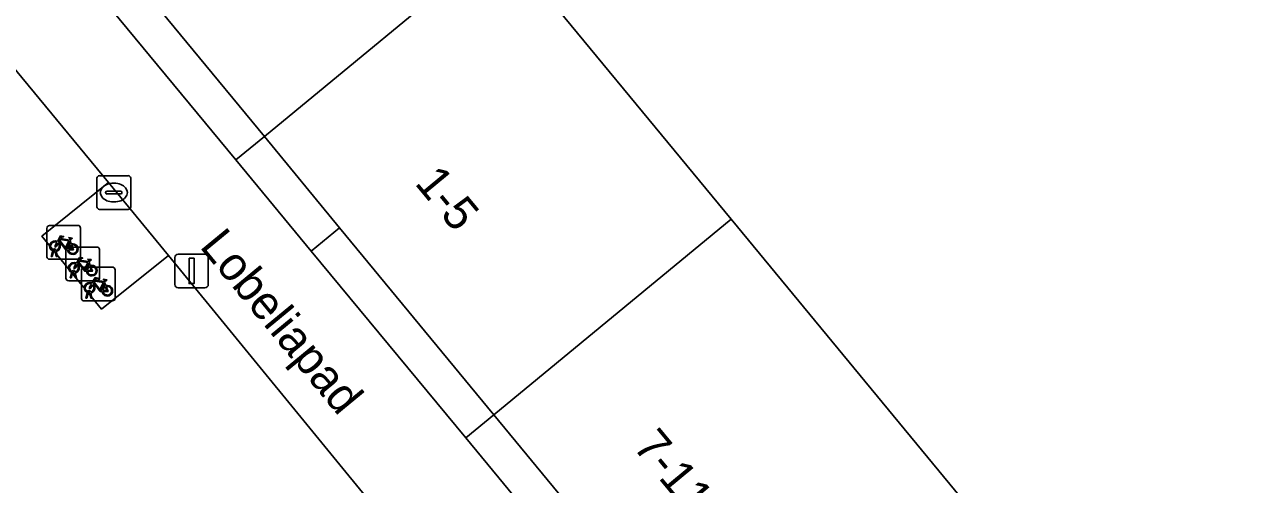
# Model space of a CAD drawing. Extents: x 162344 to 162869, y 381217 to 381818.
# Drawn here: x 162459.05 to 162495.73, y 381719.32 to 381732.95 of the extents above; entities that cross this region are included whole.
import ezdxf

# ---------------------------------------------------------------- set-up
doc = ezdxf.new("R2010")
doc.units = 0
for name, color, linetype in [('IMGEO_Fietsenrek', 7, 'Continuous'), ('IMGEO_Groenvoorziening', 7, 'Continuous'), ('IMGEO_Kolk', 7, 'Continuous'), ('IMGEO_Lichtmast', 7, 'Continuous'), ('IMGEO_Openbare_ruimte_label', 7, 'Continuous'), ('IMGEO_Pand', 7, 'Continuous'), ('IMGEO_Pand_nummerreeks', 7, 'Continuous'), ('IMGEO_Voetpad_open', 7, 'Continuous')]:
    doc.layers.add(name, color=color, linetype=linetype)

msp = doc.modelspace()

# ---------------------------------------------------------------- linework, layer by layer
at = {"layer": 'IMGEO_Fietsenrek'}
for p, q in [((162459.708, 381726.069), (162459.708, 381726.91)), ((162459.708, 381726.91), (162459.708, 381726.069)), ((162459.783, 381726.994), (162460.624, 381726.994)), ((162460.624, 381726.994), (162459.783, 381726.994)), ((162460.708, 381726.919), (162460.708, 381726.078)), ((162460.708, 381726.078), (162460.708, 381726.919)), ((162460.346, 381726.355), (162461.187, 381726.355)), ((162461.187, 381726.355), (162460.346, 381726.355)), ((162460.395, 381726.543), (162460.431, 381726.448)), ((162461.271, 381726.28), (162461.271, 381725.439)), ((162461.271, 381725.439), (162461.271, 381726.28)), ((162460.633, 381725.994), (162459.792, 381725.994)), ((162459.792, 381725.994), (162460.633, 381725.994)), ((162459.835, 381726.078), (162459.874, 381726.238)), ((162459.869, 381726.078), (162459.835, 381726.078)), ((162459.904, 381726.226), (162459.869, 381726.078)), ((162459.946, 381726.25), (162459.945, 381726.254)), ((162459.987, 381726.078), (162459.953, 381726.22)), ((162459.977, 381726.261), (162459.978, 381726.254)), ((162459.985, 381726.224), (162460.02, 381726.078)), ((162460.02, 381726.078), (162459.987, 381726.078)), ((162460.271, 381725.43), (162460.271, 381726.271)), ((162460.271, 381726.271), (162460.271, 381725.43)), ((162460.398, 381725.439), (162460.437, 381725.599)), ((162460.467, 381725.587), (162460.432, 381725.439)), ((162460.509, 381725.611), (162460.508, 381725.615)), ((162460.55, 381725.439), (162460.516, 381725.581)), ((162460.54, 381725.622), (162460.541, 381725.615)), ((162460.548, 381725.585), (162460.583, 381725.439)), ((162460.733, 381724.834), (162460.733, 381725.675)), ((162460.733, 381725.675), (162460.733, 381724.834)), ((162460.808, 381725.759), (162461.649, 381725.759)), ((162461.649, 381725.759), (162460.808, 381725.759)), ((162460.958, 381725.904), (162460.994, 381725.809)), ((162461.733, 381725.684), (162461.733, 381724.843)), ((162461.733, 381724.843), (162461.733, 381725.684)), ((162461.196, 381725.355), (162460.355, 381725.355)), ((162460.355, 381725.355), (162461.196, 381725.355)), ((162460.432, 381725.439), (162460.398, 381725.439)), ((162460.583, 381725.439), (162460.55, 381725.439)), ((162461.42, 381725.308), (162461.456, 381725.213)), ((162460.86, 381724.843), (162460.899, 381725.003)), ((162460.894, 381724.843), (162460.86, 381724.843)), ((162460.929, 381724.991), (162460.894, 381724.843)), ((162460.971, 381725.015), (162460.97, 381725.019)), ((162461.012, 381724.843), (162460.978, 381724.985)), ((162461.002, 381725.026), (162461.003, 381725.019)), ((162461.01, 381724.989), (162461.045, 381724.843)), ((162461.045, 381724.843), (162461.012, 381724.843)), ((162461.658, 381724.759), (162460.817, 381724.759)), ((162460.817, 381724.759), (162461.658, 381724.759))]:
    msp.add_line(p, q, dxfattribs=at)
for points in [[(162460.021, 381726.52), (162460.116, 381726.684), (162460.202, 381726.67), (162460.204, 381726.661), (162460.148, 381726.65), (162460.121, 381726.605), (162460.377, 381726.564)], [(162460.042, 381726.468), (162459.99, 381726.378), (162459.95, 381726.353), (162459.951, 381726.4), (162460.006, 381726.494)], [(162460.317, 381726.276), (162460.267, 381726.276), (162460.076, 381726.527), (162460.057, 381726.495)], [(162460.364, 381726.539), (162460.107, 381726.58), (162460.09, 381726.551), (162460.257, 381726.331), (162460.364, 381726.539)], [(162460.412, 381726.441), (162460.382, 381726.518), (162460.273, 381726.3), (162460.316, 381726.3)], [(162460.346, 381726.3), (162460.466, 381726.299), (162460.422, 381726.413)], [(162460.442, 381726.42), (162460.497, 381726.275), (162460.347, 381726.275)], [(162460.377, 381726.564), (162460.402, 381726.613), (162460.396, 381726.617), (162460.373, 381726.621), (162460.361, 381726.628), (162460.36, 381726.631), (162460.362, 381726.636), (162460.457, 381726.621), (162460.459, 381726.611), (162460.449, 381726.598), (162460.437, 381726.592), (162460.423, 381726.598), (162460.395, 381726.543)], [(162460.584, 381725.881), (162460.679, 381726.045), (162460.765, 381726.031), (162460.767, 381726.022), (162460.711, 381726.011), (162460.684, 381725.966), (162460.94, 381725.925)], [(162460.927, 381725.9), (162460.67, 381725.941), (162460.653, 381725.912), (162460.82, 381725.692), (162460.927, 381725.9)], [(162460.94, 381725.925), (162460.965, 381725.974), (162460.959, 381725.978), (162460.936, 381725.982), (162460.924, 381725.989), (162460.923, 381725.992), (162460.925, 381725.997), (162461.02, 381725.982), (162461.022, 381725.972), (162461.012, 381725.959), (162461, 381725.953), (162460.986, 381725.959), (162460.958, 381725.904)], [(162460.605, 381725.829), (162460.553, 381725.739), (162460.513, 381725.714), (162460.514, 381725.761), (162460.569, 381725.855)], [(162460.88, 381725.637), (162460.83, 381725.637), (162460.639, 381725.888), (162460.62, 381725.856)], [(162460.975, 381725.802), (162460.945, 381725.879), (162460.836, 381725.661), (162460.879, 381725.661)], [(162460.909, 381725.661), (162461.029, 381725.66), (162460.985, 381725.774)], [(162461.005, 381725.781), (162461.06, 381725.636), (162460.91, 381725.636)], [(162461.067, 381725.233), (162461.015, 381725.143), (162460.975, 381725.118), (162460.976, 381725.165), (162461.031, 381725.259)], [(162461.046, 381725.285), (162461.141, 381725.449), (162461.227, 381725.435), (162461.229, 381725.426), (162461.173, 381725.415), (162461.146, 381725.37), (162461.402, 381725.329)], [(162461.342, 381725.041), (162461.292, 381725.041), (162461.101, 381725.292), (162461.082, 381725.26)], [(162461.389, 381725.304), (162461.132, 381725.345), (162461.115, 381725.316), (162461.282, 381725.096), (162461.389, 381725.304)], [(162461.437, 381725.206), (162461.407, 381725.283), (162461.298, 381725.065), (162461.341, 381725.065)], [(162461.371, 381725.065), (162461.491, 381725.064), (162461.447, 381725.178)], [(162461.467, 381725.185), (162461.522, 381725.04), (162461.372, 381725.04)], [(162461.402, 381725.329), (162461.427, 381725.378), (162461.421, 381725.382), (162461.398, 381725.386), (162461.386, 381725.393), (162461.385, 381725.396), (162461.387, 381725.401), (162461.482, 381725.386), (162461.484, 381725.376), (162461.474, 381725.363), (162461.462, 381725.357), (162461.448, 381725.363), (162461.42, 381725.308)]]:
    msp.add_lwpolyline(points, dxfattribs=at)
for centre, radius, start, end in [((162459.786, 381726.916), 0.0779, 92.4484, 184.2845), ((162459.786, 381726.916), 0.0779, 92.4484, 184.2845), ((162460.63, 381726.916), 0.0779, 2.4484, 94.2845), ((162460.63, 381726.916), 0.0779, 2.4484, 94.2845), ((162459.948, 381726.379), 0.159, 62.6766, 242.1369), ((162459.948, 381726.379), 0.129, 63.3192, 238.903), ((162459.928, 381726.25), 0.0499, 12.8025, 158.6934), ((162459.948, 381726.379), 0.129, 283.6043, 43.4302), ((162459.948, 381726.379), 0.159, 283.5766, 46.6042), ((162460.349, 381726.277), 0.0779, 92.4484, 184.2845), ((162460.349, 381726.277), 0.0779, 92.4484, 184.2845), ((162460.475, 381726.295), 0.159, 113.3408, 178.3217), ((162460.475, 381726.295), 0.159, 187.0065, 105.7708), ((162460.475, 381726.295), 0.129, 113.923, 177.9556), ((162460.475, 381726.295), 0.129, 188.6715, 104.5883), ((162461.193, 381726.277), 0.0779, 2.4484, 94.2845), ((162461.193, 381726.277), 0.0779, 2.4484, 94.2845), ((162459.786, 381726.072), 0.0779, 182.4484, 274.2845), ((162459.786, 381726.072), 0.0779, 182.4484, 274.2845), ((162459.948, 381726.379), 0.159, 253.9967, 271.7867), ((162459.928, 381726.25), 0.0174, 12.8025, 163.4502), ((162459.948, 381726.379), 0.129, 253.415, 269.0204), ((162460.63, 381726.072), 0.0779, 272.4484, 4.2845), ((162460.63, 381726.072), 0.0779, 272.4484, 4.2845), ((162460.511, 381725.74), 0.159, 62.6766, 242.1369), ((162460.511, 381725.74), 0.129, 63.3192, 238.903), ((162460.491, 381725.611), 0.0499, 12.8025, 158.6934), ((162460.511, 381725.74), 0.159, 253.9967, 271.7867), ((162460.491, 381725.611), 0.0174, 12.8025, 163.4502), ((162460.511, 381725.74), 0.129, 253.415, 269.0204), ((162460.511, 381725.74), 0.129, 283.6043, 43.4302), ((162460.511, 381725.74), 0.159, 283.5766, 46.6042), ((162460.811, 381725.681), 0.0779, 92.4484, 184.2845), ((162460.811, 381725.681), 0.0779, 92.4484, 184.2845), ((162461.038, 381725.656), 0.159, 113.3408, 178.3217), ((162461.038, 381725.656), 0.159, 187.0065, 105.7708), ((162461.038, 381725.656), 0.129, 113.923, 177.9556), ((162461.038, 381725.656), 0.129, 188.6715, 104.5883), ((162461.655, 381725.681), 0.0779, 2.4484, 94.2845), ((162461.655, 381725.681), 0.0779, 2.4484, 94.2845), ((162460.349, 381725.433), 0.0779, 182.4484, 274.2845), ((162460.349, 381725.433), 0.0779, 182.4484, 274.2845), ((162460.973, 381725.144), 0.159, 62.6766, 242.1369), ((162460.973, 381725.144), 0.129, 63.3192, 238.903), ((162460.973, 381725.144), 0.129, 283.6043, 43.4302), ((162460.973, 381725.144), 0.159, 283.5766, 46.6042), ((162461.193, 381725.433), 0.0779, 272.4484, 4.2845), ((162461.193, 381725.433), 0.0779, 272.4484, 4.2845), ((162461.5, 381725.06), 0.159, 113.3408, 178.3217), ((162461.5, 381725.06), 0.159, 187.0065, 105.7708), ((162461.5, 381725.06), 0.129, 113.923, 177.9556), ((162461.5, 381725.06), 0.129, 188.6715, 104.5883), ((162460.811, 381724.837), 0.0779, 182.4484, 274.2845), ((162460.811, 381724.837), 0.0779, 182.4484, 274.2845), ((162460.953, 381725.015), 0.0499, 12.8025, 158.6934), ((162460.973, 381725.144), 0.159, 253.9967, 271.7867), ((162460.953, 381725.015), 0.0174, 12.8025, 163.4502), ((162460.973, 381725.144), 0.129, 253.415, 269.0204), ((162461.655, 381724.837), 0.0779, 272.4484, 4.2845), ((162461.655, 381724.837), 0.0779, 272.4484, 4.2845)]:
    msp.add_arc(centre, radius, start, end, dxfattribs=at)
at = {"layer": 'IMGEO_Groenvoorziening'}
for points in [[(162496.987, 381737.052), (162495.038, 381735.498), (162493.26, 381737.631), (162495.209, 381739.256), (162488.397, 381747.426), (162486.513, 381745.893), (162484.735, 381748.042), (162486.667, 381749.611), (162477.365, 381760.866), (162460.058, 381746.513), (162463.062, 381742.868), (162463.106, 381743.006), (162463.476, 381743.219), (162464.348, 381742.174), (162466.307, 381743.777), (162473.193, 381735.435), (162480.005, 381727.183), (162486.816, 381718.931), (162493.628, 381710.68), (162500.056, 381702.892)], [(162471.549, 381716.061), (162469.643, 381714.467), (162467.863, 381716.602), (162469.783, 381718.202), (162463.314, 381726.102), (162461.333, 381724.518), (162459.563, 381726.678), (162461.541, 381728.274), (162451.996, 381739.827), (162449.119, 381737.441), (162434.479, 381725.379), (162437.492, 381721.752), (162438.041, 381722.212), (162438.864, 381721.224), (162441.001, 381722.982), (162447.798, 381714.718), (162454.595, 381706.454), (162461.391, 381698.19), (162468.188, 381689.926), (162474.743, 381681.955)]]:
    msp.add_lwpolyline(points, dxfattribs=at)
for points in [[(162459.252, 381738.006), (162458.388, 381737.311), (162465.316, 381728.939), (162466.159, 381729.634)], [(162468.393, 381726.927), (162467.553, 381726.234), (162472.137, 381720.694), (162472.969, 381721.38)]]:
    msp.add_lwpolyline(points, close=True, dxfattribs=at)
at = {"layer": 'IMGEO_Kolk'}
for p, q in [((162461.268, 381728.472), (162462.12, 381728.472)), ((162461.193, 381727.546), (162461.193, 381728.398)), ((162461.681, 381728.252), (162461.706, 381728.252)), ((162462.194, 381728.398), (162462.194, 381727.546)), ((162461.452, 381727.966), (162461.452, 381727.978)), ((162461.89, 381727.929), (162461.492, 381727.929)), ((162461.495, 381728.015), (162461.893, 381728.015)), ((162461.936, 381727.978), (162461.936, 381727.966)), ((162462.12, 381727.472), (162461.268, 381727.472)), ((162461.704, 381727.692), (162461.679, 381727.692))]:
    msp.add_line(p, q, dxfattribs=at)
for points in [[(162461.268, 381728.472), (162462.12, 381728.472)], [(162461.193, 381727.546), (162461.193, 381728.398)], [(162462.194, 381728.398), (162462.194, 381727.546)], [(162462.12, 381727.472), (162461.268, 381727.472)]]:
    msp.add_lwpolyline(points, dxfattribs=at)
for centre, radius, start, end in [((162461.27, 381728.396), 0.0765, 91.552, 178.448), ((162461.27, 381728.396), 0.0765, 91.552, 178.448), ((162462.118, 381728.396), 0.0765, 1.552, 88.448), ((162462.118, 381728.396), 0.0765, 1.552, 88.448), ((162461.492, 381727.975), 0.0403, 85.8775, 175.7526), ((162461.489, 381727.965), 0.0366, 178.938, 274.7102), ((162461.893, 381727.972), 0.043, 264.8664, 352.4533), ((162461.897, 381727.977), 0.0386, 1.7309, 96.639), ((162461.27, 381727.548), 0.0765, 181.552, 268.448), ((162461.27, 381727.548), 0.0765, 181.552, 268.448), ((162462.118, 381727.548), 0.0765, 271.552, 358.448), ((162462.118, 381727.548), 0.0765, 271.552, 358.448)]:
    msp.add_arc(centre, radius, start, end, dxfattribs=at)
for centre, major_axis, ratio, start_param, end_param in [((162461.68, 381727.972), (-0.387, 0.002), 0.722429, 4.712389, 7.853982), ((162461.705, 381727.972), (-0.39, 0.002), 0.717154, 1.570796, 4.712389)]:
    msp.add_ellipse(centre, major_axis=major_axis, ratio=ratio, start_param=start_param, end_param=end_param, dxfattribs=at)
at = {"layer": 'IMGEO_Lichtmast'}
for p, q in [((162463.506, 381725.247), (162463.506, 381726.047)), ((162463.506, 381726.047), (162463.506, 381725.247)), ((162463.606, 381726.147), (162464.396, 381726.147)), ((162464.396, 381726.147), (162463.606, 381726.147)), ((162464.496, 381726.047), (162464.496, 381725.247)), ((162464.496, 381725.247), (162464.496, 381726.047)), ((162464.396, 381725.147), (162463.606, 381725.147)), ((162463.606, 381725.147), (162464.396, 381725.147))]:
    msp.add_line(p, q, dxfattribs=at)
msp.add_lwpolyline([(162463.926, 381726.022), (162464.076, 381726.022), (162464.076, 381725.272), (162463.926, 381725.272), (162463.926, 381726.022)], dxfattribs=at)
for centre, start, end in [((162463.606, 381726.047), 90, 180), ((162463.606, 381726.047), 90, 180), ((162464.396, 381726.047), 0, 90), ((162464.396, 381726.047), 360, 90), ((162463.606, 381725.247), 180, 270), ((162463.606, 381725.247), 180, 270), ((162464.396, 381725.247), 270, 0), ((162464.396, 381725.247), 270, 0)]:
    msp.add_arc(centre, 0.1, start, end, dxfattribs=at)
at = {"layer": 'IMGEO_Pand'}
for points in [[(162473.193, 381735.435), (162466.307, 381743.777), (162464.348, 381742.174), (162459.252, 381738.006), (162466.159, 381729.634)], [(162473.193, 381735.435), (162466.159, 381729.634), (162468.393, 381726.927), (162472.969, 381721.38), (162480.005, 381727.183)], [(162480.005, 381727.183), (162472.969, 381721.38), (162475.203, 381718.673), (162479.778, 381713.127), (162486.816, 381718.931)]]:
    msp.add_lwpolyline(points, close=True, dxfattribs=at)
at = {"layer": 'IMGEO_Voetpad_open'}
for points in [[(162474.375, 381717.99), (162472.137, 381720.694), (162467.553, 381726.234), (162465.316, 381728.939), (162458.388, 381737.311), (162457.62, 381738.466), (162454.645, 381742.024), (162451.996, 381739.827), (162461.541, 381728.274), (162463.314, 381726.102), (162469.783, 381718.202), (162471.549, 381716.061), (162476.506, 381710.061), (162478.262, 381707.898), (162483.232, 381701.86), (162484.979, 381699.692), (162489.486, 381694.198), (162492.218, 381696.426), (162488.017, 381701.503), (162485.78, 381704.207), (162481.196, 381709.747), (162478.958, 381712.451)], [(162466.159, 381729.634), (162465.316, 381728.939), (162467.553, 381726.234), (162468.393, 381726.927)], [(162461.541, 381728.274), (162459.563, 381726.678), (162461.333, 381724.518), (162463.314, 381726.102)], [(162472.969, 381721.38), (162472.137, 381720.694), (162474.375, 381717.99), (162475.203, 381718.673)]]:
    msp.add_lwpolyline(points, close=True, dxfattribs=at)

# ---------------------------------------------------------------- texts
at = {"layer": 'IMGEO_Openbare_ruimte_label'}
msp.add_text('Lobeliapad', height=1, rotation=309.4829, dxfattribs=at).set_placement((162464.216, 381726.367))
at = {"layer": 'IMGEO_Pand_nummerreeks'}
for s, rotation, p in [('1-5', 309.6313, (162470.596, 381728.24)), ('7-11', 309.6599, (162477.068, 381720.427))]:
    msp.add_text(s, height=1, rotation=rotation, dxfattribs=at).set_placement(p)

doc.saveas('drawing.dxf')
